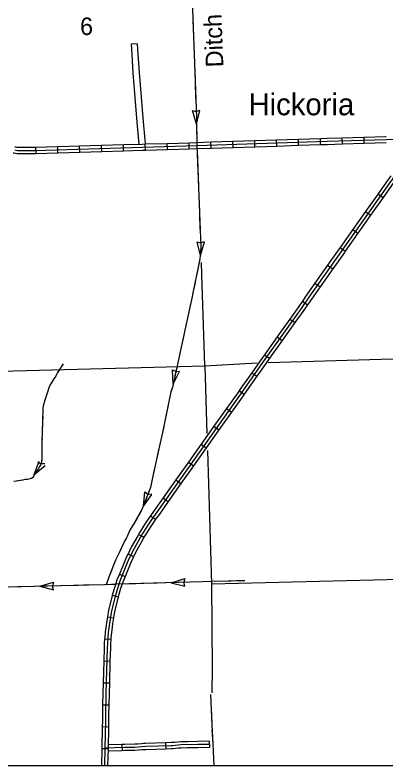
# Model space of a CAD drawing. Extents: x 1164457 to 1439835, y 1590918 to 1773502.
# Drawn here: x 1331207 to 1340153, y 1614471 to 1632574 of the extents above; entities that cross this region are included whole.
import ezdxf

# ---------------------------------------------------------------- set-up
doc = ezdxf.new("R2010")
doc.units = 0
for name, color, linetype in [('Level 24', 7, 'Continuous'), ('Level 32', 7, 'Continuous'), ('Level 43', 7, 'Continuous'), ('Level 45', 7, 'Continuous'), ('Level 46', 7, 'Continuous'), ('Level 5', 7, 'Continuous'), ('R_Draft', 7, 'Continuous')]:
    doc.layers.add(name, color=color, linetype=linetype)

msp = doc.modelspace()

# ---------------------------------------------------------------- linework, layer by layer
at = {"layer": 'Level 32'}
for p, q in [((1335936, 1629364), (1335931, 1629514)), ((1336464, 1629381), (1336459, 1629531)), ((1336992, 1629399), (1336987, 1629549)), ((1337520, 1629416), (1337515, 1629566)), ((1338047, 1629433), (1338042, 1629583)), ((1338575, 1629450), (1338570, 1629600)), ((1339103, 1629467), (1339098, 1629617)), ((1339630, 1629483), (1339626, 1629633)), ((1331714, 1629238), (1331710, 1629388)), ((1332242, 1629253), (1332237, 1629403)), ((1332770, 1629269), (1332765, 1629418)), ((1333297, 1629284), (1333293, 1629434)), ((1333825, 1629299), (1333821, 1629449)), ((1334353, 1629315), (1334348, 1629465)), ((1334881, 1629331), (1334876, 1629481)), ((1335409, 1629347), (1335404, 1629497)), ((1339962, 1628265), (1340084, 1628179)), ((1339657, 1627834), (1339780, 1627747)), ((1339353, 1627402), (1339476, 1627316)), ((1339049, 1626971), (1339171, 1626884)), ((1338744, 1626540), (1338867, 1626453)), ((1338440, 1626108), (1338562, 1626022)), ((1338136, 1625675), (1338260, 1625590)), ((1337833, 1625245), (1337955, 1625158)), ((1337526, 1624815), (1337648, 1624728)), ((1337220, 1624385), (1337342, 1624298)), ((1336916, 1623952), (1337038, 1623866)), ((1336613, 1623520), (1336736, 1623434)), ((1336308, 1623089), (1336430, 1623003)), ((1336003, 1622659), (1336125, 1622572)), ((1335697, 1622228), (1335820, 1622141)), ((1335392, 1621797), (1335514, 1621710)), ((1335086, 1621366), (1335209, 1621280)), ((1334781, 1620936), (1334903, 1620849)), ((1334476, 1620505), (1334598, 1620418)), ((1334185, 1620053), (1334317, 1619983)), ((1333933, 1619588), (1334067, 1619520)), ((1333723, 1619096), (1333862, 1619040)), ((1333551, 1618590), (1333695, 1618547)), ((1333435, 1618066), (1333583, 1618041)), ((1333369, 1617535), (1333518, 1617525)), ((1333347, 1617005), (1333497, 1617000)), ((1333332, 1616477), (1333482, 1616472)), ((1333319, 1615948), (1333469, 1615945)), ((1333311, 1615420), (1333461, 1615417)), ((1333300, 1614892), (1333450, 1614889))]:
    msp.add_line(p, q, dxfattribs=at)
for points in [[(1335404, 1629497), (1335593, 1629503), (1335931, 1629514)], [(1335595, 1629428), (1338734, 1629531), (1340153, 1629574), (1340765, 1629600), (1340771, 1629601)], [(1335931, 1629514), (1336459, 1629531)], [(1336459, 1629531), (1336987, 1629549)], [(1340931, 1629520), (1340881, 1629444), (1340383, 1628725), (1340226, 1628510), (1339087, 1626895), (1338293, 1625771), (1338109, 1625503), (1337644, 1624851), (1337177, 1624196), (1336662, 1623459)], [(1336987, 1629549), (1337515, 1629566)], [(1337515, 1629566), (1338042, 1629583)], [(1338042, 1629583), (1338570, 1629600)], [(1338570, 1629600), (1338731, 1629606), (1339098, 1629617)], [(1339098, 1629617), (1339626, 1629633)], [(1339626, 1629633), (1340151, 1629649), (1340153, 1629650)], [(1339630, 1629483), (1340156, 1629500), (1340159, 1629500)], [(1331203, 1629323), (1331234, 1629316), (1331268, 1629311), (1331323, 1629310), (1331469, 1629312), (1331696, 1629312), (1334277, 1629387), (1335595, 1629428)], [(1331207, 1629400), (1331222, 1629395), (1331247, 1629390), (1331274, 1629386), (1331324, 1629385), (1331468, 1629387), (1331695, 1629387), (1331710, 1629388)], [(1331710, 1629388), (1332237, 1629403)], [(1332237, 1629403), (1332765, 1629418)], [(1332765, 1629418), (1333293, 1629434)], [(1333293, 1629434), (1333821, 1629449)], [(1333821, 1629449), (1334275, 1629462), (1334348, 1629465)], [(1334348, 1629465), (1334876, 1629481)], [(1334353, 1629315), (1334881, 1629331)], [(1334876, 1629481), (1335404, 1629497)], [(1334881, 1629331), (1335409, 1629347)], [(1335409, 1629347), (1335598, 1629353), (1335936, 1629364)], [(1335936, 1629364), (1336464, 1629381)], [(1336464, 1629381), (1336992, 1629399)], [(1336992, 1629399), (1337520, 1629416)], [(1337520, 1629416), (1338047, 1629433)], [(1338047, 1629433), (1338575, 1629450)], [(1338575, 1629450), (1338736, 1629456), (1339103, 1629467)], [(1339103, 1629467), (1339630, 1629483)], [(1331164, 1629256), (1331184, 1629250), (1331221, 1629242), (1331262, 1629236), (1331322, 1629235), (1331469, 1629237), (1331697, 1629237), (1331714, 1629238)], [(1331714, 1629238), (1332242, 1629253)], [(1332242, 1629253), (1332770, 1629269)], [(1332770, 1629269), (1333297, 1629284)], [(1333297, 1629284), (1333825, 1629299)], [(1333825, 1629299), (1334279, 1629313), (1334353, 1629315)], [(1340269, 1628696), (1340165, 1628553), (1339962, 1628265)], [(1340390, 1628608), (1340286, 1628466), (1340084, 1628179)], [(1339962, 1628265), (1339657, 1627834)], [(1340084, 1628179), (1339780, 1627747)], [(1339657, 1627834), (1339353, 1627402)], [(1339780, 1627747), (1339476, 1627316)], [(1339353, 1627402), (1339049, 1626971)], [(1339476, 1627316), (1339171, 1626884)], [(1339049, 1626971), (1339026, 1626939), (1338744, 1626540)], [(1339171, 1626884), (1339149, 1626852), (1338867, 1626453)], [(1338744, 1626540), (1338440, 1626108)], [(1338867, 1626453), (1338562, 1626022)], [(1338440, 1626108), (1338231, 1625814), (1338136, 1625675)], [(1338562, 1626022), (1338354, 1625728), (1338260, 1625590)], [(1338136, 1625675), (1338048, 1625546), (1337833, 1625245)], [(1338260, 1625590), (1338171, 1625460), (1337955, 1625158)], [(1337833, 1625245), (1337583, 1624895), (1337526, 1624815)], [(1337955, 1625158), (1337705, 1624808), (1337648, 1624728)], [(1337526, 1624815), (1337220, 1624385)], [(1337648, 1624728), (1337342, 1624298)], [(1337220, 1624385), (1337116, 1624239), (1336916, 1623952)], [(1337342, 1624298), (1337239, 1624153), (1337038, 1623866)], [(1336916, 1623952), (1336613, 1623520)], [(1337038, 1623866), (1336736, 1623434)], [(1336662, 1623459), (1334627, 1620588), (1334492, 1620399), (1334409, 1620276), (1334370, 1620213), (1334280, 1620073), (1334233, 1619983), (1334079, 1619710), (1333977, 1619509), (1333939, 1619422), (1333913, 1619366), (1333736, 1618929), (1333683, 1618770), (1333619, 1618557), (1333537, 1618212), (1333484, 1617905), (1333456, 1617691), (1333446, 1617564), (1333436, 1617422), (1333431, 1617310), (1333400, 1616224), (1333389, 1615705), (1333389, 1615550), (1333375, 1614899), (1333366, 1614471)], [(1336613, 1623520), (1336601, 1623502), (1336308, 1623089)], [(1336736, 1623434), (1336723, 1623416), (1336430, 1623003)], [(1336308, 1623089), (1336003, 1622659)], [(1336430, 1623003), (1336125, 1622572)], [(1336003, 1622659), (1335697, 1622228)], [(1336125, 1622572), (1335820, 1622141)], [(1335697, 1622228), (1335392, 1621797)], [(1335820, 1622141), (1335514, 1621710)], [(1335392, 1621797), (1335086, 1621366)], [(1335514, 1621710), (1335209, 1621280)], [(1335086, 1621366), (1334781, 1620936)], [(1335209, 1621280), (1334903, 1620849)], [(1334781, 1620936), (1334566, 1620632), (1334476, 1620505)], [(1334903, 1620849), (1334688, 1620545), (1334598, 1620418)], [(1334476, 1620505), (1334431, 1620441), (1334346, 1620317), (1334306, 1620253), (1334215, 1620111), (1334185, 1620053)], [(1334598, 1620418), (1334554, 1620356), (1334472, 1620235), (1334433, 1620173), (1334345, 1620035), (1334317, 1619983)], [(1334185, 1620053), (1334167, 1620019), (1334012, 1619745), (1333933, 1619588)], [(1334317, 1619983), (1334299, 1619947), (1334145, 1619675), (1334067, 1619520)], [(1333933, 1619588), (1333909, 1619541), (1333870, 1619453), (1333845, 1619396), (1333723, 1619096)], [(1334067, 1619520), (1334045, 1619477), (1334007, 1619392), (1333982, 1619337), (1333862, 1619040)], [(1333723, 1619096), (1333666, 1618955), (1333611, 1618793), (1333551, 1618590)], [(1333862, 1619040), (1333807, 1618903), (1333754, 1618747), (1333695, 1618547)], [(1333551, 1618590), (1333547, 1618576), (1333463, 1618228), (1333435, 1618066)], [(1333695, 1618547), (1333692, 1618537), (1333610, 1618197), (1333583, 1618041)], [(1333435, 1618066), (1333410, 1617917), (1333381, 1617699), (1333371, 1617570), (1333369, 1617535)], [(1333583, 1618041), (1333558, 1617894), (1333531, 1617683), (1333521, 1617558), (1333518, 1617525)], [(1333369, 1617535), (1333361, 1617426), (1333356, 1617313), (1333347, 1617005)], [(1333518, 1617525), (1333511, 1617417), (1333506, 1617307), (1333497, 1617000)], [(1333347, 1617005), (1333332, 1616477)], [(1333497, 1617000), (1333482, 1616472)], [(1333332, 1616477), (1333325, 1616226), (1333319, 1615948)], [(1333482, 1616472), (1333475, 1616222), (1333469, 1615945)], [(1333319, 1615948), (1333314, 1615706), (1333314, 1615551), (1333311, 1615420)], [(1333469, 1615945), (1333464, 1615704), (1333464, 1615549), (1333461, 1615417)], [(1333311, 1615420), (1333300, 1614900), (1333300, 1614892)], [(1333461, 1615417), (1333450, 1614897), (1333450, 1614889)], [(1333300, 1614892), (1333291, 1614471)], [(1333450, 1614889), (1333441, 1614471)]]:
    msp.add_lwpolyline(points, dxfattribs=at)
at = {"layer": 'Level 43'}
for p, q in [((1335586, 1629941), (1335485, 1630269)), ((1335485, 1630269), (1335575, 1630248)), ((1335663, 1630275), (1335576, 1630249)), ((1335586, 1629941), (1335663, 1630275)), ((1335593, 1627103), (1335682, 1627082)), ((1335678, 1626775), (1335602, 1627109)), ((1335678, 1626775), (1335779, 1627103)), ((1335770, 1627109), (1335683, 1627082)), ((1335020, 1623676), (1335004, 1624018)), ((1335004, 1624018), (1335085, 1623977)), ((1335020, 1623676), (1335177, 1623981)), ((1335177, 1623981), (1335086, 1623976)), ((1331670, 1621496), (1331791, 1621817)), ((1331754, 1621801), (1331833, 1621756)), ((1331925, 1621755), (1331834, 1621755)), ((1331670, 1621496), (1331935, 1621714)), ((1334303, 1620736), (1334340, 1621077)), ((1334303, 1620736), (1334505, 1621013)), ((1334340, 1621077), (1334413, 1621023)), ((1334505, 1621013), (1334415, 1621022)), ((1331804, 1618802), (1332133, 1618898)), ((1332133, 1618898), (1332112, 1618809)), ((1334970, 1618888), (1335299, 1618987)), ((1334970, 1618888), (1335304, 1618809)), ((1335299, 1618987), (1335278, 1618898)), ((1335304, 1618809), (1335278, 1618897)), ((1331804, 1618802), (1332137, 1618721)), ((1332137, 1618721), (1332112, 1618808))]:
    msp.add_line(p, q, dxfattribs=at)
for points in [[(1335425, 1634462), (1335580, 1630104), (1335595, 1629428), (1335686, 1626983), (1335682, 1626868), (1335676, 1626777), (1335664, 1626696), (1335622, 1626496), (1335506, 1625914), (1335463, 1625710), (1335327, 1625088), (1335009, 1623625), (1334967, 1623489)], [(1335497, 1632447), (1335511, 1632051)], [(1335516, 1631920), (1335530, 1631524)], [(1335534, 1631392), (1335549, 1630996)], [(1335553, 1630864), (1335567, 1630468)], [(1335572, 1630337), (1335580, 1630104), (1335584, 1629941)], [(1335587, 1629809), (1335591, 1629611)], [(1335591, 1629611), (1335594, 1629503)], [(1335601, 1629281), (1335615, 1628885)], [(1335620, 1628753), (1335635, 1628358)], [(1335640, 1628226), (1335654, 1627830)], [(1335659, 1627698), (1335674, 1627302)], [(1335679, 1627170), (1335686, 1626983), (1335682, 1626868), (1335676, 1626777), (1335675, 1626775)], [(1335653, 1626645), (1335622, 1626496), (1335613, 1626451)], [(1335613, 1626451), (1335575, 1626257)], [(1335549, 1626127), (1335506, 1625914), (1335469, 1625739)], [(1335441, 1625610), (1335357, 1625223)], [(1335329, 1625094), (1335327, 1625088), (1335245, 1624707)], [(1335217, 1624578), (1335132, 1624192)], [(1332368, 1624163), (1332261, 1624003), (1332233, 1623957), (1332222, 1623937), (1332209, 1623905), (1332191, 1623867), (1332145, 1623805), (1332093, 1623725), (1332069, 1623687), (1332048, 1623651), (1332036, 1623626), (1332019, 1623588), (1331995, 1623506), (1331925, 1623290), (1331885, 1623146), (1331879, 1623108), (1331872, 1622768), (1331856, 1622300), (1331857, 1621941), (1331852, 1621860), (1331845, 1621805), (1331837, 1621769), (1331826, 1621729), (1331801, 1621687), (1331774, 1621641), (1331720, 1621565), (1331689, 1621518), (1331650, 1621453), (1331634, 1621428), (1331607, 1621405), (1331573, 1621392), (1331511, 1621378), (1331479, 1621376), (1331454, 1621373), (1331420, 1621368), (1331385, 1621361), (1331175, 1621327)], [(1335104, 1624063), (1335020, 1623676)], [(1332198, 1623882), (1332191, 1623867), (1332145, 1623805), (1332093, 1623725), (1332069, 1623687), (1332048, 1623651), (1332036, 1623626), (1332019, 1623588), (1332004, 1623539)], [(1334986, 1623548), (1334967, 1623489)], [(1331965, 1623413), (1331925, 1623290), (1331885, 1623146), (1331879, 1623108), (1331877, 1623029)], [(1334967, 1623489), (1334831, 1622824), (1334767, 1622514), (1334691, 1622192), (1334529, 1621454), (1334476, 1621183), (1334269, 1620650)], [(1334967, 1623489), (1334928, 1623295)], [(1334901, 1623166), (1334831, 1622824), (1334822, 1622778)], [(1331875, 1622897), (1331872, 1622768), (1331863, 1622501)], [(1334795, 1622649), (1334767, 1622514), (1334708, 1622263)], [(1331859, 1622369), (1331856, 1622300), (1331857, 1621974)], [(1334678, 1622134), (1334593, 1621747)], [(1331850, 1621842), (1331845, 1621805), (1331837, 1621769), (1331826, 1621729), (1331801, 1621687), (1331774, 1621641), (1331720, 1621565), (1331689, 1621518), (1331674, 1621493)], [(1334565, 1621618), (1334529, 1621454), (1334485, 1621230)], [(1331394, 1621363), (1331385, 1621361), (1331199, 1621331)], [(1331588, 1621398), (1331573, 1621392), (1331511, 1621378), (1331479, 1621376), (1331454, 1621373), (1331420, 1621368), (1331394, 1621363)], [(1334446, 1621105), (1334303, 1620736)], [(1334269, 1620650), (1334080, 1620327), (1333976, 1620159), (1333924, 1620045), (1333911, 1620002), (1333892, 1619967), (1333870, 1619930), (1333848, 1619890), (1333724, 1619627), (1333631, 1619429), (1333478, 1619047), (1333414, 1618862), (1333395, 1618828)], [(1334249, 1620615), (1334149, 1620445)], [(1334149, 1620445), (1334080, 1620327), (1334048, 1620275)], [(1333978, 1620162), (1333976, 1620159), (1333924, 1620045), (1333911, 1620002), (1333892, 1619967), (1333870, 1619930), (1333848, 1619890), (1333808, 1619805)], [(1333752, 1619686), (1333724, 1619627), (1333631, 1619429), (1333589, 1619325)], [(1333540, 1619203), (1333478, 1619047), (1333406, 1618840)], [(1336751, 1618936), (1335937, 1618919), (1335726, 1618910), (1333666, 1618850), (1333653, 1618851), (1333601, 1618842), (1333530, 1618843), (1333363, 1618838), (1332619, 1618821), (1330727, 1618777)], [(1332728, 1618823), (1332619, 1618821), (1332332, 1618814)], [(1333256, 1618836), (1332860, 1618826)], [(1333585, 1618842), (1333530, 1618843), (1333387, 1618839)], [(1333629, 1618847), (1333601, 1618842), (1333585, 1618842)], [(1334310, 1618869), (1333914, 1618857)], [(1334838, 1618884), (1334442, 1618873)], [(1335366, 1618900), (1334970, 1618888)], [(1335894, 1618917), (1335726, 1618910), (1335498, 1618904)], [(1336421, 1618929), (1336025, 1618921)], [(1336751, 1618936), (1336553, 1618932)], [(1331672, 1618799), (1331276, 1618789)], [(1332200, 1618811), (1331804, 1618802)], [(1335920, 1616197), (1335950, 1615465), (1335974, 1615001), (1336002, 1614471)], [(1335920, 1616197), (1335928, 1615999)], [(1335934, 1615867), (1335950, 1615471)], [(1335957, 1615339), (1335974, 1615001), (1335977, 1614944)], [(1335984, 1614812), (1336002, 1614471)]]:
    msp.add_lwpolyline(points, dxfattribs=at)
at = {"layer": 'Level 45'}
for p, q in [((1334837, 1615030), (1334842, 1614880)), ((1335893, 1615067), (1335897, 1614917)), ((1333782, 1614989), (1333788, 1614839))]:
    msp.add_line(p, q, dxfattribs=at)
for points in [[(1334837, 1615030), (1334354, 1615012), (1334308, 1615010)], [(1335365, 1615056), (1335209, 1615053), (1335132, 1615048), (1335059, 1615040), (1335012, 1615035), (1334970, 1615035), (1334837, 1615030)], [(1335893, 1615067), (1335616, 1615060), (1335365, 1615056)], [(1335895, 1614992), (1335618, 1614985), (1335212, 1614978), (1335138, 1614974), (1335067, 1614966), (1335016, 1614960), (1334971, 1614960), (1334357, 1614937), (1334261, 1614932), (1334175, 1614923), (1334096, 1614920), (1333855, 1614916), (1333375, 1614899)], [(1333788, 1614839), (1333448, 1614826)], [(1333782, 1614989), (1333451, 1614977)], [(1334308, 1615010), (1334255, 1615007), (1334169, 1614998), (1334094, 1614994), (1333853, 1614991), (1333782, 1614989)], [(1334316, 1614860), (1334267, 1614858), (1334180, 1614848), (1334098, 1614845), (1333857, 1614841), (1333788, 1614839)], [(1334842, 1614880), (1334360, 1614862), (1334316, 1614860)], [(1335368, 1614906), (1335215, 1614903), (1335144, 1614899), (1335076, 1614891), (1335021, 1614885), (1334973, 1614885), (1334842, 1614880)], [(1335897, 1614917), (1335619, 1614910), (1335368, 1614906)]]:
    msp.add_lwpolyline(points, dxfattribs=at)
at = {"layer": 'Level 46'}
for points in [[(1334156, 1631878), (1334006, 1631870), (1334021, 1631624), (1334049, 1631179), (1334148, 1629989), (1334185, 1629552), (1334194, 1629460)], [(1334156, 1631878), (1334170, 1631633), (1334199, 1631190), (1334297, 1630001), (1334334, 1629566), (1334345, 1629465)]]:
    msp.add_lwpolyline(points, dxfattribs=at)
at = {"layer": 'Level 5'}
for points in [[(1335788, 1624114), (1335710, 1626316), (1335701, 1626607)], [(1337312, 1624201), (1340036, 1624281), (1340987, 1624293)], [(1330554, 1623981), (1335788, 1624114)], [(1335788, 1624114), (1337043, 1624188)], [(1335788, 1624114), (1335836, 1622487)], [(1335848, 1622073), (1335944, 1618861)], [(1335944, 1618861), (1341153, 1618990)], [(1335944, 1618861), (1335961, 1616817), (1335951, 1616234)]]:
    msp.add_lwpolyline(points, dxfattribs=at)
at = {"layer": 'R_Draft'}
msp.add_lwpolyline([(1246398, 1678582), (1349820, 1678582), (1349820, 1614471), (1246398, 1614471)], close=True, dxfattribs=at)

# ---------------------------------------------------------------- texts
at = {"layer": 'Level 24'}
msp.add_text('Hickoria', height=528, dxfattribs=at).set_placement((1336837, 1630158))
at = {"layer": 'Level 43'}
msp.add_text('Ditch', height=422, rotation=92.1682, dxfattribs=at).set_placement((1336233, 1631321))
at = {"layer": 'Level 5'}
msp.add_text('6', height=422, dxfattribs=at).set_placement((1332775, 1632092))

doc.saveas('drawing.dxf')
